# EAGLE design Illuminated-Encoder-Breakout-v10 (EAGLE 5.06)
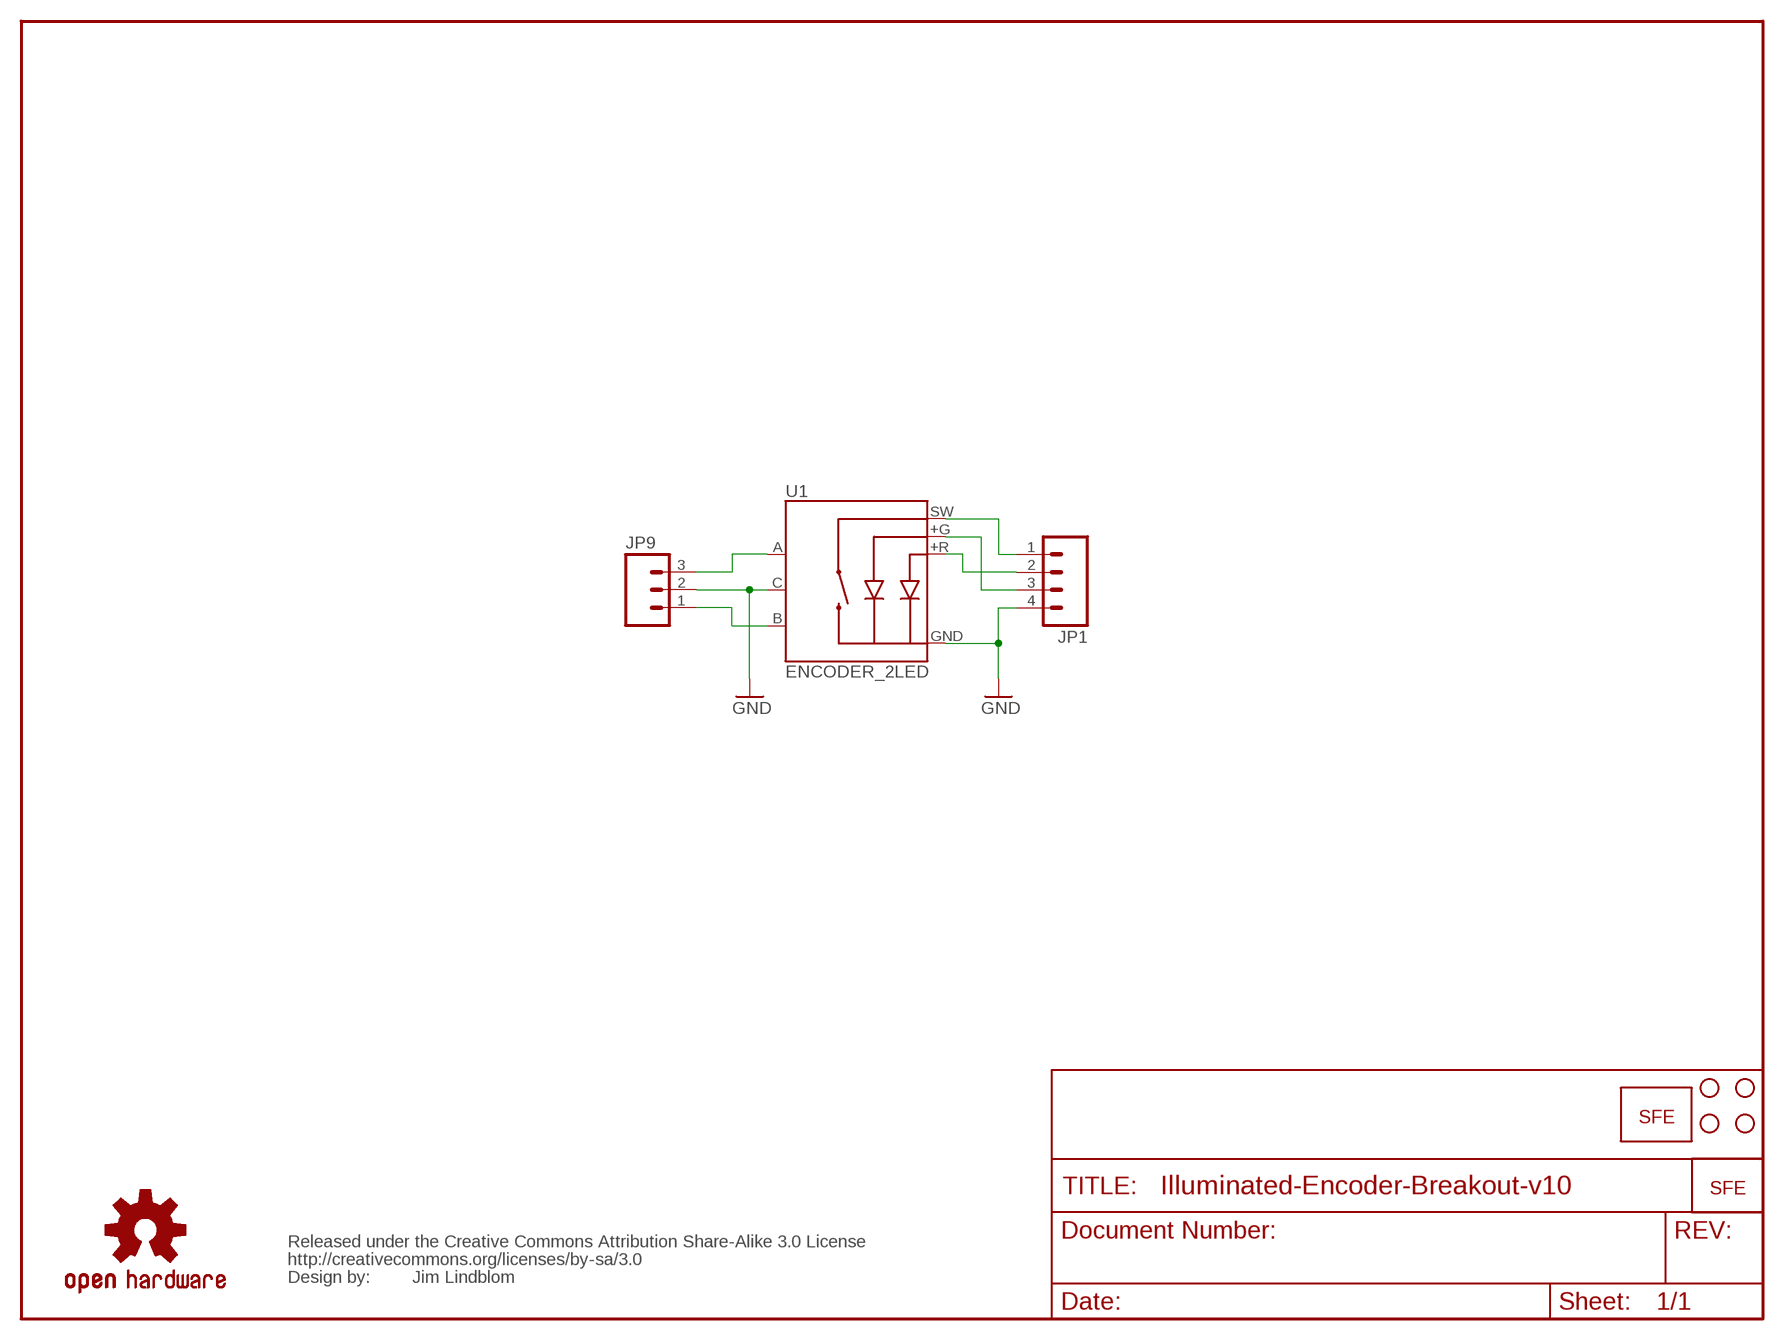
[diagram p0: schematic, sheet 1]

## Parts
JP1  M04PTH  [1X04]
JP3  STAND-OFF  [STAND-OFF]
JP4  STAND-OFF  [STAND-OFF]
JP5  STAND-OFF  [STAND-OFF]
JP6  STAND-OFF  [STAND-OFF]
JP7  LOGO-SFENW2  [SFE-NEW-WEB]
JP8  LOGO-SFESK  [SFE-LOGO-FLAME]
JP9  M03PTH  [1X03]
U1  ENCODER_2LED  [ENCODER_LED_2]
U$1  CREATIVE_COMMONS  [CREATIVE_COMMONS]
U$2  OSHW-LOGOM  [OSHW-LOGO-M]

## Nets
A: JP9.3 U1.A
B: JP9.1 U1.B
G: JP1.3 U1.+G
GND: JP1.4 JP9.2 U1.C U1.GND(-)
R: JP1.2 U1.+R
SW: JP1.1 U1.SW

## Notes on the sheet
- Jim Lindblom

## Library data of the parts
JP1 = SparkFun:M04: Header 4 Standard 4-pin 0.1" header. Use with straight break away headers (SKU : PRT-00116), right angle break away headers (PRT-00553), swiss pins (PRT-00743), machine pins (PRT-00117), and female headers (PRT-00115). Molex polarized connector foot print use with SKU : PRT-08231 with associated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
JP3-JP6 = SparkFun:STAND-OFF: Stand Off
JP7 JP8 = SparkFun:LOGO-SFE: Spark Fun Electronics PCB Logo
JP9 = SparkFun:M03: Header 3 Standard 3-pin 0.1" header. Use with straight break away headers (SKU : PRT-00116), right angle break away headers (PRT-00553), swiss pins (PRT-00743), machine pins (PRT-00117), and female headers (PRT-00115). Molex polarized connector foot print use with SKU : PRT-08232 with associated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
U1 = SparkFun:ENCODER_2LED: Illuminated Rotary Encoder w/ 2 LEDs
U$1 = SparkFun:CREATIVE_COMMONS
U$2 = SparkFun:OSHW-LOGO: Open Source Hardware Logo This logo indicates the piece of hardware it is found on incorporates a OSHW license and/or adheres to the definition of open source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

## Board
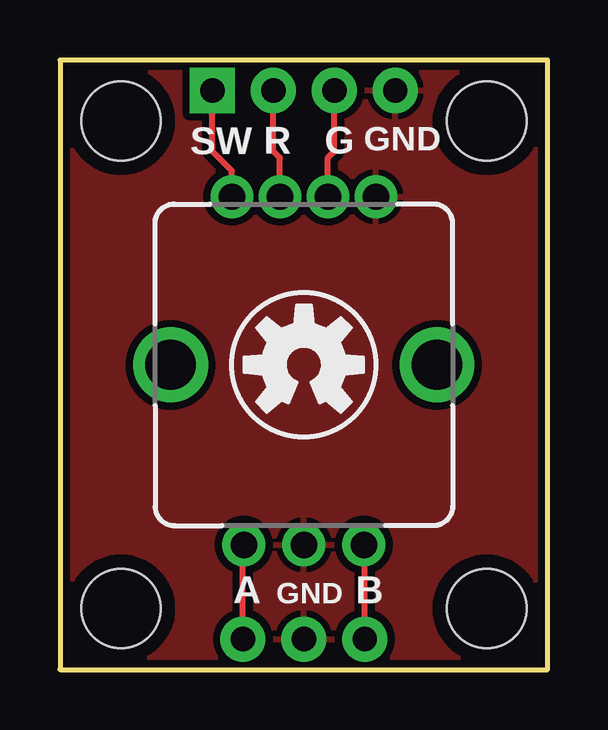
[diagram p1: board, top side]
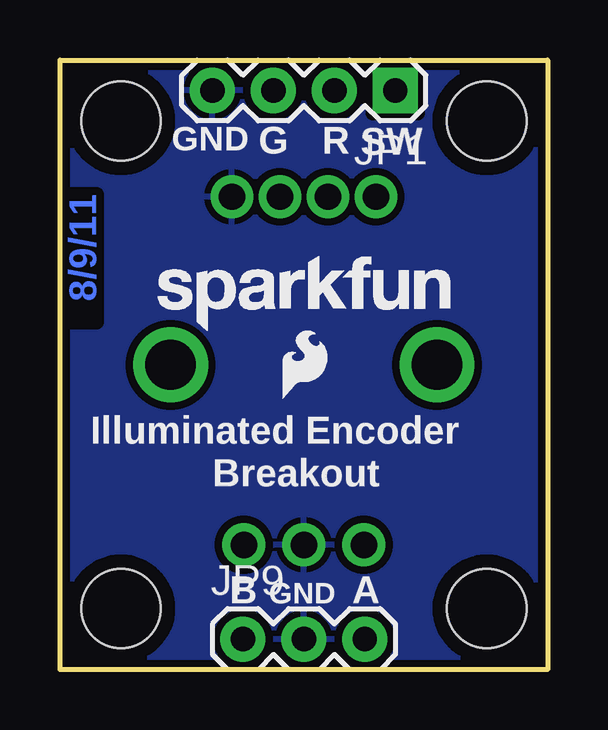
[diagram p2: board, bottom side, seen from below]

Size 20.32 x 25.4 mm. Coordinates in mm from the lower left corner, seen from the top.
Outline: 0,0 20.32,0 20.32,25.4 0,25.4 0,0
Copper layers (1*16): Top 0.035mm / dielectric 1.5mm / Bottom 0.035mm
Design rules "SparkFun": minimum track width 8mil, minimum drill 20mil, track to track 8mil, track to pad 8mil, pad to pad 8mil, via to via 8mil, smd to smd 8mil, copper to edge 8mil, drill to drill 8mil, minimum pad ring 12mil, minimum via ring 10mil, stop-mask expansion 4mil, vias tented up to drill 20mil, thermal gap 10mil

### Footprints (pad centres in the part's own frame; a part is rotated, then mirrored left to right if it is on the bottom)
1X04 = drill 1.016 pad 1.88 square: 1 0,0 | drill 1.016 pad 1.88 round: 2 2.54,0; 3 5.08,0; 4 7.62,0
STAND-OFF = hole 3.302: 0,0
1X03 = drill 1.016 pad 1.88 round: 1 0,0; 2 2.54,0; 3 5.08,0
ENCODER_LED_2 = drill 1.1 pad 1.778 round: +G 1,7; +R -1,7; GND 3,7; SW -3,7 | drill 1.1 pad 1.8 round: A -2.5,-7.5; B 2.5,-7.5; C 0,-7.5 | drill 2.1 round: P$1 -5.55,0; P$2 5.55,0

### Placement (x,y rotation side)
JP1  6.35,24.13 180 bottom
JP3  2.54,2.54 0 top
JP4  17.78,2.54 0 top
JP5  17.78,22.86 0 top
JP6  2.54,22.86 0 top
JP7  16.26,14.1 0 bottom
JP8  11.05,11.3 0 bottom
JP9  12.7,1.27 0 bottom
U1  10.16,12.7 0 top
U$1  not placed on the board
U$2  10.16,12.7 0 top

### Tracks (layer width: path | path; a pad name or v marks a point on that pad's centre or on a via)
A
  Top 0.254: JP9.3 7.62,5.16 U1.A
B
  Top 0.254: JP9.1 12.7,5.16 U1.B
G
  Top 0.254: U1.+G 11.16,21.32 11.43,21.59 JP1.3
GND
  pour Bottom (isolate 0.305): 0,25.4 0,0 20.32,0 20.32,25.4
  pour Top (isolate 0.305): 0,25.4 0,0 20.32,0 20.32,25.4
R
  Top 0.254: U1.+R 9.16,21.32 8.89,21.59 JP1.2
SW
  Top 0.254: U1.SW 7.16,20.78 6.35,21.59 JP1.1

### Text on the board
Bottom: 8/9/11
tPlace: GND | SW | R | G | A | GND | B
bPlace: SW | R | G | GND | Illuminated Encoder | Breakout | A | GND | B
